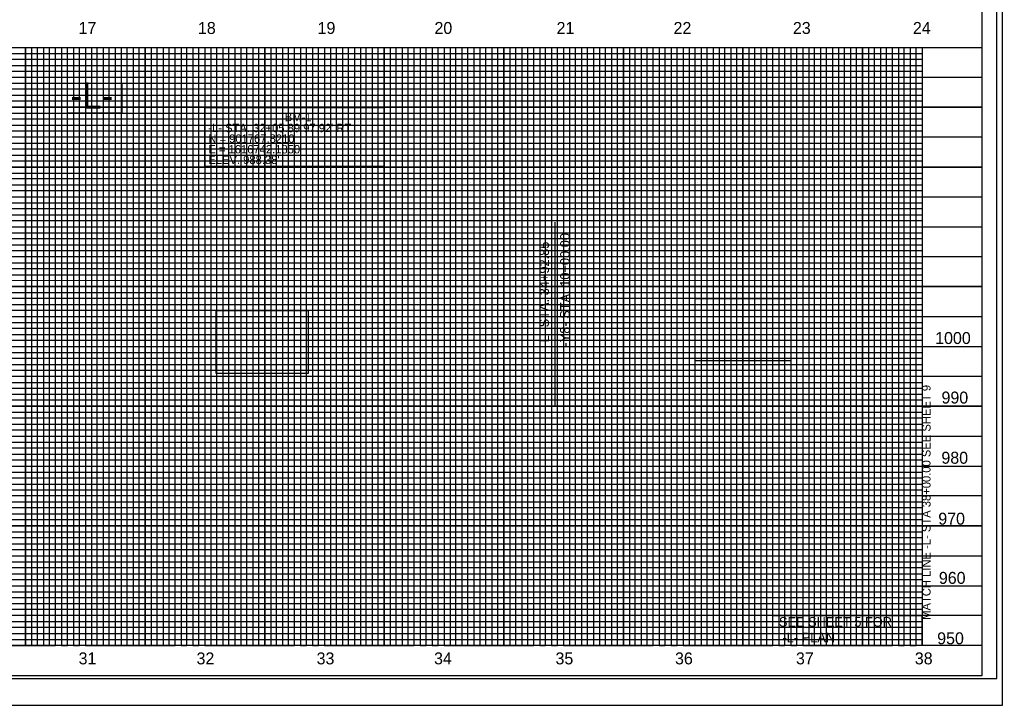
# Model space of a CAD drawing. Extents: x 1623313 to 1628771, y 891211 to 901910.
# Drawn here: x 1624175 to 1624997, y 900759 to 901333 of the extents above; entities that cross this region are included whole.
import ezdxf

# ---------------------------------------------------------------- set-up
doc = ezdxf.new("R2010")
doc.units = 0
for name, color, linetype in [('Default', 7, 'Continuous'), ('Matchline', 7, 'Continuous'), ('Matchline Text', 7, 'Continuous'), ('Prop DSN Text', 7, 'Continuous'), ('Prop PHM Black Shape', 7, 'Continuous'), ('Sheet Cutting Line CELL', 7, 'Continuous'), ('Sheet DOT Grid CELL', 7, 'Continuous'), ('Sheet Layout Profile Border Port 2', 7, 'Continuous'), ('Sheet Plot Border Inside CELL', 7, 'Continuous'), ('Sheet Plot Border Outside CELL', 7, 'Continuous'), ('Sheet Profile CELL', 7, 'Continuous'), ('Sheet Profile Grid Major CELL', 7, 'Continuous'), ('Sheet Profile Grid Middle CELL', 7, 'Continuous'), ('Sheet Profile Grid Minor CELL', 7, 'Continuous')]:
    doc.layers.add(name, color=color, linetype=linetype)

msp = doc.modelspace()

# ---------------------------------------------------------------- linework, layer by layer
at = {"layer": 'Matchline'}
msp.add_line((1624929.95, 901309.54), (1624929.95, 900809.54), dxfattribs=at)
at = {"layer": 'Prop DSN Text'}
for points in [[(1624214.95, 901279.54), (1624260.36, 901279.54), (1624260.36, 901254.45), (1624214.95, 901254.45)], [(1624929.95, 900809.54), (1624804.95, 900809.54), (1624804.95, 900834.54), (1624929.95, 900834.54)]]:
    msp.add_lwpolyline(points, close=True, dxfattribs=at)
msp.add_lwpolyline([(1624622.79, 901009.45), (1624622.8, 901009.46), (1624622.93, 901163.42)], dxfattribs=at)
at = {"layer": 'Prop PHM Black Shape'}
for points in [[(1624214.95, 901279.45), (1624260.36, 901279.45), (1624260.36, 901254.45), (1624214.95, 901254.45)], [(1624329.95, 901259.35), (1624479.71, 901259.35), (1624479.71, 901209.9), (1624329.95, 901209.9)], [(1624739.95, 901099.45), (1624819.95, 901099.45), (1624819.95, 901047.43), (1624739.95, 901047.43)], [(1624339.26, 901089.45), (1624416.28, 901089.45), (1624416.28, 901036.79), (1624339.26, 901036.79)], [(1624804.93, 900834.45), (1624929.71, 900834.45), (1624929.71, 900809.49), (1624804.93, 900809.49)]]:
    msp.add_lwpolyline(points, close=True, dxfattribs=at)
at = {"layer": 'Sheet Cutting Line CELL'}
msp.add_line((1623312.95, 900759.45), (1624996.95, 900759.45), dxfattribs=at)
at = {"layer": 'Sheet DOT Grid CELL'}
for p, q in [((1623479.95, 901309.45), (1624979.83, 901309.45)), ((1624179.95, 901309.45), (1624179.95, 900809.45)), ((1624229.95, 901309.45), (1624229.95, 900809.45)), ((1624279.95, 901309.45), (1624279.95, 900809.45)), ((1624329.95, 901309.45), (1624329.95, 900809.45)), ((1624379.95, 901309.45), (1624379.95, 900809.45)), ((1624429.95, 901309.45), (1624429.95, 900809.45)), ((1624479.95, 901309.45), (1624479.95, 900809.45)), ((1624529.95, 901309.45), (1624529.95, 900809.45)), ((1624579.95, 901309.45), (1624579.95, 900809.45)), ((1624629.95, 901309.45), (1624629.95, 900809.45)), ((1624679.95, 901309.45), (1624679.95, 900809.45)), ((1624729.95, 901309.45), (1624729.95, 900809.45)), ((1624779.95, 901309.45), (1624779.95, 900809.45)), ((1624829.95, 901309.45), (1624829.95, 900809.45)), ((1624879.95, 901309.45), (1624879.95, 900809.45)), ((1624929.95, 901309.45), (1624929.95, 900809.45)), ((1623479.95, 901259.45), (1624979.83, 901259.45)), ((1623479.95, 901209.45), (1624979.83, 901209.45)), ((1623479.95, 901159.45), (1624979.83, 901159.45)), ((1623479.95, 901109.45), (1624979.83, 901109.45)), ((1623479.95, 901059.45), (1624979.83, 901059.45)), ((1623479.95, 901009.45), (1624979.83, 901009.45)), ((1623479.95, 900959.45), (1624979.83, 900959.45)), ((1623479.95, 900909.45), (1624979.83, 900909.45)), ((1623479.95, 900859.45), (1624979.83, 900859.45))]:
    msp.add_line(p, q, dxfattribs=at)
at = {"layer": 'Sheet Layout Profile Border Port 2'}
msp.add_lwpolyline([(1623529.95, 901309.45), (1624929.95, 901309.45), (1624929.95, 900809.45), (1623529.95, 900809.45)], close=True, dxfattribs=at)
at = {"layer": 'Sheet Plot Border Inside CELL'}
msp.add_lwpolyline([(1623325.95, 900781.9), (1624992.45, 900781.9), (1624992.45, 901837), (1623325.95, 901837)], close=True, dxfattribs=at)
at = {"layer": 'Sheet Plot Border Outside CELL'}
msp.add_lwpolyline([(1623312.95, 900759.45), (1624996.95, 900759.45), (1624996.95, 901859.45), (1623312.95, 901859.45)], close=True, dxfattribs=at)
at = {"layer": 'Sheet Profile CELL'}
for p, q in [((1623479.95, 901309.45), (1624979.95, 901309.45)), ((1624979.95, 900809.45), (1623479.95, 900809.45)), ((1623479.95, 900784.45), (1624979.95, 900784.45))]:
    msp.add_line(p, q, dxfattribs=at)
msp.add_lwpolyline([(1624979.95, 901834.45), (1623479.95, 901834.45), (1623479.95, 900784.45), (1624979.95, 900784.45)], close=True, dxfattribs=at)
at = {"layer": 'Sheet Profile Grid Major CELL'}
for p, q in [((1624179.95, 901309.45), (1624229.95, 901309.45)), ((1624279.95, 901309.45), (1624329.95, 901309.45)), ((1624379.95, 901309.45), (1624429.95, 901309.45)), ((1624479.95, 901309.45), (1624529.95, 901309.45)), ((1624579.95, 901309.45), (1624629.95, 901309.45)), ((1624679.95, 901309.45), (1624729.95, 901309.45)), ((1624779.95, 901309.45), (1624829.95, 901309.45)), ((1624879.95, 901309.45), (1624929.95, 901309.45)), ((1624879.95, 900809.45), (1624879.95, 900809.45))]:
    msp.add_line(p, q, dxfattribs=at)
for points in [[(1624129.95, 900809.45), (1624179.95, 900809.45), (1624179.95, 901309.45), (1624229.95, 901309.45), (1624229.95, 900809.45), (1624279.95, 900809.45), (1624279.95, 901309.45), (1624329.95, 901309.45), (1624329.95, 900809.45), (1624379.95, 900809.45), (1624379.95, 901309.45), (1624429.95, 901309.45), (1624429.95, 900809.45), (1624479.95, 900809.45), (1624479.95, 901309.45), (1624529.95, 901309.45), (1624529.95, 900809.45), (1624579.95, 900809.45), (1624579.95, 901309.45), (1624629.95, 901309.45), (1624629.95, 900809.45), (1624679.95, 900809.45), (1624679.95, 901309.45), (1624729.95, 901309.45), (1624729.95, 900809.45), (1624779.95, 900809.45), (1624779.95, 901309.45), (1624829.95, 901309.45), (1624829.95, 900809.45), (1624879.95, 900809.45), (1624879.95, 900809.45), (1624879.95, 901309.45), (1624929.95, 901309.45), (1624929.95, 900809.45)], [(1624979.95, 901259.45), (1623479.95, 901259.45)], [(1624979.95, 901209.45), (1623479.95, 901209.45), (1623479.95, 901159.45), (1624979.95, 901159.45)], [(1624979.95, 901109.45), (1623479.95, 901109.45), (1623479.95, 901059.45), (1624979.95, 901059.45)], [(1624979.95, 901009.45), (1623479.95, 901009.45), (1623479.95, 900959.45), (1624979.95, 900959.45)], [(1624979.95, 900909.45), (1623479.95, 900909.45), (1623479.95, 900909.45), (1623479.95, 900859.45), (1624979.95, 900859.45)], [(1624979.95, 900809.45), (1623479.95, 900809.45)]]:
    msp.add_lwpolyline(points, dxfattribs=at)
at = {"layer": 'Sheet Profile Grid Middle CELL'}
for points in [[(1624154.95, 900809.45), (1624204.95, 900809.45), (1624204.95, 901309.45), (1624254.95, 901309.45), (1624254.95, 900809.45), (1624304.95, 900809.45), (1624304.95, 901309.45), (1624354.95, 901309.45), (1624354.95, 900809.45), (1624404.95, 900809.45), (1624404.95, 901309.45), (1624454.95, 901309.45), (1624454.95, 900809.45), (1624504.95, 900809.45), (1624504.95, 901309.45), (1624554.95, 901309.45), (1624554.95, 900809.45), (1624604.95, 900809.45), (1624604.95, 901309.45), (1624654.95, 901309.45), (1624654.95, 900809.45), (1624704.95, 900809.45), (1624704.95, 901309.45), (1624754.95, 901309.45), (1624754.95, 900809.45), (1624804.95, 900809.45), (1624804.95, 901309.45), (1624854.95, 901309.45), (1624854.95, 900809.45), (1624904.95, 900809.45), (1624904.95, 901309.45)], [(1623479.95, 901284.45), (1624979.95, 901284.45)], [(1624979.95, 901234.45), (1623479.95, 901234.45), (1623479.95, 901184.45), (1624979.95, 901184.45)], [(1624979.95, 901134.45), (1623479.95, 901134.45), (1623479.95, 901084.45), (1624979.95, 901084.45)], [(1624979.95, 901034.45), (1623479.95, 901034.45), (1623479.95, 900984.45), (1624979.95, 900984.45)], [(1624979.95, 900934.45), (1623479.95, 900934.45), (1623479.95, 900884.45), (1624979.95, 900884.45)], [(1624979.95, 900834.45), (1623479.95, 900834.45)]]:
    msp.add_lwpolyline(points, dxfattribs=at)
at = {"layer": 'Sheet Profile Grid Minor CELL'}
for p, q in [((1623529.95, 901304.45), (1624929.95, 901304.45)), ((1624929.95, 901299.45), (1623529.95, 901299.45)), ((1623529.95, 901294.45), (1624929.95, 901294.45)), ((1624929.95, 901289.45), (1623529.95, 901289.45)), ((1623529.95, 901279.45), (1624929.95, 901279.45)), ((1624929.95, 901274.45), (1623529.95, 901274.45)), ((1623529.95, 901269.45), (1624929.95, 901269.45)), ((1624929.95, 901264.45), (1623529.95, 901264.45)), ((1623529.95, 901254.45), (1624929.95, 901254.45)), ((1624929.95, 901249.45), (1623529.95, 901249.45)), ((1623529.95, 901244.45), (1624929.95, 901244.45)), ((1624929.95, 901239.45), (1623529.95, 901239.45)), ((1623529.95, 901229.45), (1624929.95, 901229.45)), ((1624929.95, 901224.45), (1623529.95, 901224.45)), ((1623529.95, 901219.45), (1624929.95, 901219.45)), ((1624929.95, 901214.45), (1623529.95, 901214.45)), ((1623529.95, 901204.45), (1624929.95, 901204.45)), ((1624929.95, 901199.45), (1623529.95, 901199.45)), ((1623529.95, 901194.45), (1624929.95, 901194.45)), ((1624929.95, 901189.45), (1623529.95, 901189.45)), ((1623529.95, 901179.45), (1624929.95, 901179.45)), ((1624929.95, 901174.45), (1623529.95, 901174.45)), ((1623529.95, 901169.45), (1624929.95, 901169.45)), ((1624929.95, 901164.45), (1623529.95, 901164.45)), ((1623529.95, 901154.45), (1624929.95, 901154.45)), ((1624929.95, 901149.45), (1623529.95, 901149.45)), ((1623529.95, 901144.45), (1624929.95, 901144.45)), ((1624929.95, 901139.45), (1623529.95, 901139.45)), ((1623529.95, 901129.45), (1624929.95, 901129.45)), ((1624929.95, 901124.45), (1623529.95, 901124.45)), ((1623529.95, 901119.45), (1624929.95, 901119.45)), ((1624929.95, 901114.45), (1623529.95, 901114.6)), ((1623529.95, 901104.45), (1624929.95, 901104.45)), ((1624929.95, 901099.45), (1623529.95, 901099.45)), ((1623529.95, 901094.45), (1624929.95, 901094.45)), ((1624929.95, 901089.45), (1623529.95, 901089.45)), ((1623529.95, 901079.45), (1624929.95, 901079.45)), ((1624929.95, 901074.45), (1623529.95, 901074.45)), ((1623529.95, 901069.45), (1624929.95, 901069.45)), ((1624929.95, 901064.45), (1623529.95, 901064.45)), ((1623529.95, 901054.45), (1624929.95, 901054.45)), ((1624929.95, 901049.45), (1623529.95, 901049.45)), ((1623529.95, 901044.45), (1624929.95, 901044.45)), ((1624929.95, 901039.45), (1623529.95, 901039.45)), ((1623529.95, 901029.45), (1624929.95, 901029.45)), ((1624929.95, 901024.45), (1623529.95, 901024.45)), ((1623529.95, 901019.45), (1624929.95, 901019.45)), ((1624929.95, 901014.45), (1623529.95, 901014.45)), ((1623529.95, 901004.45), (1624929.95, 901004.45)), ((1624929.95, 900999.45), (1623529.95, 900999.45)), ((1623529.95, 900994.45), (1624929.95, 900994.45)), ((1624929.95, 900989.45), (1623529.95, 900989.45)), ((1623529.95, 900979.45), (1624929.95, 900979.45)), ((1624929.95, 900974.45), (1623529.95, 900974.45)), ((1623529.95, 900969.45), (1624929.95, 900969.45)), ((1624929.95, 900964.45), (1623529.95, 900964.45)), ((1623529.95, 900954.45), (1624929.95, 900954.45)), ((1624929.95, 900949.45), (1623529.95, 900949.45)), ((1623529.95, 900944.45), (1624929.95, 900944.45)), ((1624929.95, 900939.45), (1623529.95, 900939.45)), ((1623529.95, 900929.45), (1624929.95, 900929.45)), ((1624929.95, 900924.45), (1623529.95, 900924.45)), ((1623529.95, 900919.45), (1624929.95, 900919.45)), ((1624929.95, 900914.45), (1623529.95, 900914.45)), ((1623529.95, 900904.45), (1624929.95, 900904.45)), ((1624929.95, 900899.45), (1623529.95, 900899.45)), ((1623529.95, 900894.45), (1624929.95, 900894.45)), ((1624929.95, 900889.45), (1623529.95, 900889.45)), ((1623529.95, 900879.45), (1624929.95, 900879.45)), ((1624929.95, 900874.45), (1623529.95, 900874.45)), ((1623529.95, 900869.45), (1624929.95, 900869.45)), ((1624929.95, 900864.45), (1623529.95, 900864.45)), ((1623529.95, 900854.45), (1624929.95, 900854.45)), ((1624929.95, 900849.45), (1623529.95, 900849.45)), ((1623529.95, 900844.45), (1624929.95, 900844.45)), ((1624929.95, 900839.45), (1623529.95, 900839.45)), ((1623529.95, 900829.45), (1624929.95, 900829.45)), ((1624929.95, 900824.45), (1623529.95, 900824.45)), ((1623529.95, 900819.45), (1624929.95, 900819.45)), ((1623529.95, 900814.45), (1624929.95, 900814.45)), ((1624929.95, 900814.45), (1624929.95, 900814.45))]:
    msp.add_line(p, q, dxfattribs=at)
for points in [[(1624174.95, 901309.45), (1624184.95, 901309.45), (1624184.95, 900809.45), (1624184.95, 900809.45), (1624189.95, 900809.45), (1624189.95, 901309.45), (1624194.95, 901309.45), (1624194.95, 900809.45), (1624199.95, 900809.45), (1624199.95, 901309.45), (1624209.95, 901309.45), (1624209.95, 900809.45), (1624214.95, 900809.45), (1624214.95, 901309.45), (1624219.95, 901309.45), (1624219.95, 900809.45), (1624224.95, 900809.45), (1624224.95, 901309.45), (1624234.95, 901309.45), (1624234.95, 900809.45), (1624239.95, 900809.45), (1624239.95, 901309.45), (1624244.95, 901309.45), (1624244.95, 900809.45), (1624249.95, 900809.45), (1624249.95, 901309.45), (1624259.95, 901309.45), (1624259.95, 900809.45), (1624264.95, 900809.45), (1624264.95, 901309.45), (1624269.95, 901309.45), (1624269.95, 900809.45), (1624274.95, 900809.45), (1624274.95, 901309.45), (1624284.95, 901309.45), (1624284.95, 900809.45), (1624289.95, 900809.45), (1624289.95, 901309.45), (1624294.95, 901309.45), (1624294.95, 900809.45), (1624299.95, 900809.45), (1624299.95, 901309.45), (1624309.95, 901309.45), (1624309.95, 900809.45), (1624314.95, 900809.45), (1624314.95, 901309.45), (1624319.95, 901309.45), (1624319.95, 900809.45), (1624324.95, 900809.45), (1624324.95, 901309.45), (1624334.95, 901309.45), (1624334.95, 900809.45), (1624339.65, 900810), (1624339.95, 900809.45), (1624339.95, 901309.45), (1624344.95, 901309.45), (1624344.95, 900809.45), (1624349.95, 900809.45), (1624349.95, 901309.45), (1624359.95, 901309.45), (1624359.95, 900809.45), (1624364.95, 900809.45)], [(1624364.95, 900809.45), (1624364.95, 901309.45), (1624369.95, 901309.45), (1624369.95, 900809.45), (1624374.95, 900809.45), (1624374.95, 901309.45), (1624384.95, 901309.45), (1624384.95, 900809.45), (1624389.95, 900809.45), (1624389.95, 901309.45), (1624394.95, 901309.45), (1624394.95, 900809.45), (1624399.95, 900809.45), (1624399.95, 901309.45), (1624409.95, 901309.45), (1624409.95, 900809.45), (1624414.95, 900809.45), (1624414.95, 901309.45), (1624419.95, 901309.45), (1624419.95, 900809.45), (1624424.95, 900809.45), (1624424.95, 901309.45), (1624434.95, 901309.45), (1624434.95, 900809.45), (1624439.95, 900809.45), (1624439.95, 901309.45), (1624444.95, 901309.45), (1624444.95, 900809.45), (1624449.95, 900809.45), (1624449.95, 901309.45), (1624459.95, 901309.45), (1624459.95, 900809.45), (1624464.95, 900809.45), (1624464.95, 901309.45), (1624469.95, 901309.45), (1624469.95, 900809.45), (1624474.95, 900809.45), (1624474.95, 901309.45), (1624484.95, 901309.45), (1624484.95, 900809.45), (1624489.95, 900809.45), (1624489.95, 901309.45), (1624494.95, 901309.45), (1624494.95, 900809.45), (1624499.95, 900809.45), (1624499.95, 901309.45), (1624509.95, 901309.45), (1624509.95, 900809.45), (1624514.95, 900809.45), (1624514.95, 901309.45), (1624519.95, 901309.45), (1624519.95, 900809.45), (1624524.95, 900809.45), (1624524.95, 901309.45), (1624534.95, 901309.45), (1624534.95, 900809.45), (1624539.95, 900809.45), (1624539.95, 901309.45), (1624544.95, 901309.45), (1624544.95, 900809.45), (1624549.95, 900809.45), (1624549.95, 901309.45), (1624559.95, 901309.45), (1624559.95, 900809.45), (1624564.95, 900809.45), (1624564.95, 901309.45), (1624569.95, 901309.45), (1624569.95, 900809.45), (1624574.95, 900809.45), (1624574.95, 901309.45), (1624584.95, 901309.45), (1624584.95, 900809.45), (1624589.95, 900809.45), (1624589.95, 901309.45), (1624594.95, 901309.45), (1624594.95, 900809.45), (1624599.95, 900809.45), (1624599.95, 901309.45), (1624609.95, 901309.45), (1624609.95, 900809.45), (1624614.95, 900809.45), (1624614.95, 901309.45), (1624619.95, 901309.45), (1624619.95, 900809.45), (1624624.95, 900809.45), (1624624.95, 901309.45), (1624634.95, 901309.45), (1624634.95, 900809.45), (1624639.95, 900809.45), (1624639.95, 901309.45), (1624644.95, 901309.45), (1624644.95, 900809.45), (1624649.95, 900809.45), (1624649.95, 901309.45), (1624659.95, 901309.45), (1624659.95, 900809.45), (1624664.95, 900809.45), (1624664.95, 901309.45), (1624669.95, 901309.45), (1624669.95, 900809.45)], [(1624669.95, 900809.45), (1624674.95, 900809.45), (1624674.95, 901309.45), (1624684.95, 901309.45), (1624684.95, 900809.45), (1624689.95, 900809.45), (1624689.95, 901309.45), (1624694.95, 901309.45), (1624694.95, 900809.45), (1624699.95, 900809.45), (1624699.95, 901309.45), (1624709.95, 901309.45), (1624709.95, 900809.45), (1624714.95, 900809.45), (1624714.95, 901309.45), (1624719.95, 901309.45), (1624719.95, 900809.45), (1624724.95, 900809.45), (1624724.95, 901309.45), (1624734.95, 901309.45), (1624734.95, 900809.45), (1624739.95, 900809.45), (1624739.95, 901309.45), (1624744.95, 901309.45), (1624744.95, 900809.45), (1624749.95, 900809.45), (1624749.95, 901309.45), (1624759.95, 901309.45), (1624759.95, 900809.45), (1624764.95, 900809.45), (1624764.95, 901309.45), (1624769.95, 901309.45), (1624769.95, 900809.45), (1624774.95, 900809.45), (1624774.95, 901309.45), (1624784.95, 901309.45), (1624784.95, 900809.45), (1624789.95, 900809.45), (1624789.95, 901309.45), (1624794.95, 901309.45), (1624794.95, 900809.45), (1624799.95, 900809.45), (1624799.95, 901309.45), (1624809.95, 901309.45), (1624809.95, 900809.45), (1624814.95, 900809.45), (1624814.95, 901309.45), (1624819.95, 901309.45), (1624819.95, 900809.45), (1624824.95, 900809.45), (1624824.95, 901309.45), (1624834.95, 901309.45), (1624834.95, 900809.45), (1624839.95, 900809.45), (1624839.95, 901309.45), (1624844.95, 901309.45), (1624844.95, 900809.45), (1624849.95, 900809.45), (1624849.95, 901309.45), (1624859.95, 901309.45), (1624859.95, 900809.45), (1624864.95, 900809.45), (1624864.95, 901309.45), (1624869.95, 901309.45), (1624869.95, 900809.45), (1624874.95, 900809.45), (1624874.95, 901309.45), (1624884.95, 901309.45), (1624884.95, 900809.45), (1624889.95, 900809.45), (1624889.95, 901309.45), (1624894.95, 901309.45), (1624894.95, 900809.45), (1624899.95, 900809.45), (1624899.95, 901309.45), (1624909.95, 901309.45), (1624909.95, 900809.45), (1624914.95, 900809.45), (1624914.95, 901309.45), (1624919.95, 901309.45), (1624919.95, 900809.45), (1624924.95, 900809.45), (1624924.95, 901309.45), (1624929.95, 901309.45)]]:
    msp.add_lwpolyline(points, dxfattribs=at)

# ---------------------------------------------------------------- texts
at = {"layer": 'Default'}
for s, p in [('17', (1624224.28, 901320.7)), ('18', (1624324.11, 901320.7)), ('19', (1624424.21, 901320.7)), ('20', (1624521.95, 901320.7)), ('21', (1624624.09, 901320.7)), ('22', (1624721.92, 901320.7)), ('23', (1624821.77, 901320.7)), ('24', (1624922.15, 901320.7)), ('1000', (1624940.77, 901061.5)), ('990', (1624946.07, 901011.72)), ('980', (1624945.97, 900961.42)), ('970', (1624943.38, 900910.48)), ('960', (1624943.86, 900860.98)), ('950', (1624942.45, 900810.48)), ('31', (1624224.28, 900793.69)), ('32', (1624322.93, 900793.69)), ('33', (1624423.37, 900793.69)), ('34', (1624521.61, 900793.69)), ('35', (1624623.19, 900793.69)), ('36', (1624723.15, 900793.69)), ('37', (1624824.32, 900793.69)), ('38', (1624923.75, 900793.69))]:
    msp.add_text(s, height=10, dxfattribs=at).set_placement(p)
at = {"layer": 'Matchline Text'}
msp.add_text('MATCH LINE -L- STA 38+00.00 SEE SHEET 9', height=7, rotation=90, dxfattribs=at).set_placement((1624936.89, 900830.91))
at = {"layer": 'Prop DSN Text'}
for s, height, p in [('-L-', 21.875, (1624217.53, 901258.33)), ('BM-1 ', 7, (1624396.8, 901247.74)), ("-L- STA. 32+05.89 97.92' RT", 7, (1624332.8, 901238.6)), ('N = 901767.8210', 7, (1624332.8, 901229.73)), ('E = 1616742.1850', 7, (1624332.8, 901220.85)), ("ELEV. 988.38'", 7, (1624332.8, 901211.98)), ('SEE SHEET 5 FOR', 8, (1624810.09, 900825.2)), (' -L- PLAN', 8, (1624810.09, 900812.2))]:
    msp.add_text(s, height=height, dxfattribs=at).set_placement(p)
for s, p in [('-Y8- STA. 10+00.00', (1624635.07, 901059.4)), ('-L- STA. 34+92.85', (1624617.7, 901059.4))]:
    msp.add_text(s, height=8, rotation=90, dxfattribs=at).set_placement(p)

doc.saveas('drawing.dxf')
